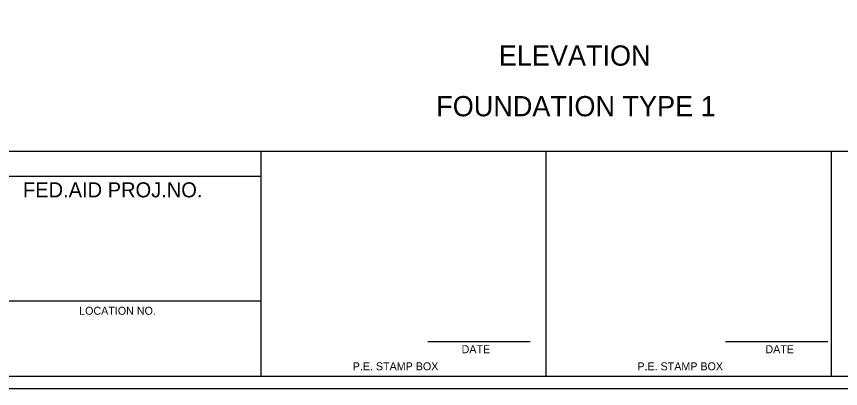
# Model space of a CAD drawing. Extents: x 99888 to 103177, y 100000 to 102076.
# Drawn here: x 101256 to 102071, y 100000 to 100368 of the extents above; entities that cross this region are included whole.
import ezdxf

# ---------------------------------------------------------------- set-up
doc = ezdxf.new("R2010")
doc.units = 0
for name, color, linetype in [('Level 20', 7, 'Continuous'), ('SH_GI_PlotLimits', 7, 'Continuous'), ('SH_GI_SheetBorder', 7, 'Continuous'), ('SH_GI_SheetTextInCells', 7, 'Continuous')]:
    doc.layers.add(name, color=color, linetype=linetype)

msp = doc.modelspace()

# ---------------------------------------------------------------- linework, layer by layer
at = {"layer": 'SH_GI_PlotLimits'}
msp.add_lwpolyline([(99888.5, 100000), (103150, 100000), (103150, 102075.5), (99888.5, 102075.5)], close=True, dxfattribs=at)
msp.add_lwpolyline([(99888.5, 100000), (103150, 100000), (103150, 102075.5), (99888.5, 102075.5)], close=True, dxfattribs=at)
at = {"layer": 'SH_GI_SheetBorder'}
for p, q in [((100024.39, 100234.91), (103137.64, 100234.91)), ((100024.39, 100234.91), (103137.64, 100234.91)), ((101498.32, 100012.35), (101498.32, 100234.91)), ((101498.32, 100012.35), (101498.32, 100234.91)), ((101780.22, 100012.35), (101780.22, 100234.91)), ((101780.22, 100012.35), (101780.22, 100234.91)), ((102062.13, 100234.91), (102062.13, 100012.35)), ((102062.13, 100234.91), (102062.13, 100012.35)), ((100024.39, 100210.18), (101498.32, 100210.18)), ((100024.39, 100210.18), (101498.32, 100210.18)), ((101498.32, 100086.54), (101101.01, 100086.54)), ((101498.32, 100086.54), (101101.01, 100086.54)), ((101663.11, 100046.61), (101764.26, 100046.61)), ((101663.11, 100046.61), (101764.26, 100046.61)), ((101957.52, 100046.61), (102058.67, 100046.61)), ((101957.52, 100046.61), (102058.67, 100046.61)), ((100024.39, 100012.35), (103137.64, 100012.35)), ((100024.39, 100012.35), (103137.64, 100012.35))]:
    msp.add_line(p, q, dxfattribs=at)

# ---------------------------------------------------------------- texts
at = {"layer": 'Level 20'}
for s, p in [('ELEVATION', (101733.34, 100319.46)), ('ELEVATION', (101733.34, 100319.46)), ('FOUNDATION TYPE 1', (101671.47, 100269.38))]:
    msp.add_text(s, height=20, dxfattribs=at).set_placement(p)
at = {"layer": 'SH_GI_SheetTextInCells'}
for s, height, p in [('FED.AID PROJ.NO.', 14.8369, (101262.82, 100189.17)), ('FED.AID PROJ.NO.', 14.8369, (101262.82, 100189.17)), ('LOCATION NO.', 7.913, (101318.41, 100072.98)), ('LOCATION NO.', 7.913, (101318.41, 100072.98)), ('DATE', 7.913, (101696.6, 100034.9)), ('DATE', 7.913, (101696.6, 100034.9)), ('DATE', 7.913, (101997, 100034.9)), ('DATE', 7.913, (101997, 100034.9)), ('P.E. STAMP BOX', 7.913, (101588.93, 100018.01)), ('P.E. STAMP BOX', 7.913, (101588.93, 100018.01)), ('P.E. STAMP BOX', 7.913, (101870.4, 100018.01)), ('P.E. STAMP BOX', 7.913, (101870.4, 100018.01))]:
    msp.add_text(s, height=height, dxfattribs=at).set_placement(p)

doc.saveas('drawing.dxf')
